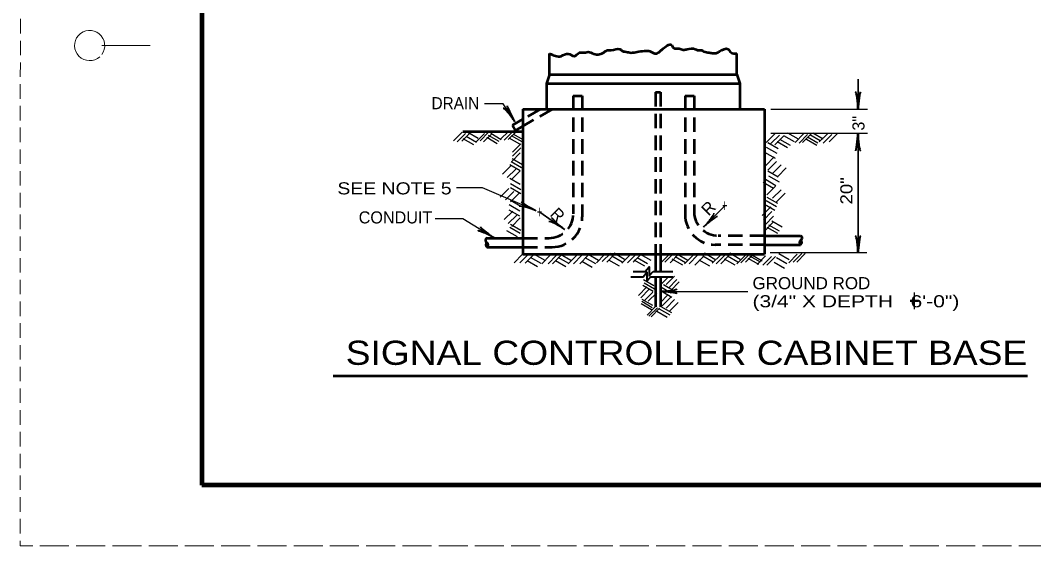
# Model space of a CAD drawing. Extents: x -560 to 120, y 26 to 466.
# Drawn here: x -559.8 to -392.1, y 25.8 to 112.8 of the extents above; entities that cross this region are included whole.
import ezdxf
from ezdxf.enums import TextEntityAlignment as Align

# ---------------------------------------------------------------- set-up
doc = ezdxf.new("R2010")
doc.units = 0
doc.header["$LTSCALE"] = 0.8
doc.linetypes.add('LONG_DASHED', pattern=[7.5, 6, -1.5])
doc.linetypes.add('MEDIUM_DASHED', pattern=[4.5, 3, -1.5])
doc.layers.add('1', color=7, linetype='Continuous', lineweight=53)
doc.layers.add('61', color=7, linetype='Continuous', lineweight=35)

msp = doc.modelspace()

# ---------------------------------------------------------------- linework, layer by layer
at = {"layer": '1', "linetype": 'MEDIUM_DASHED', "lineweight": 13}
msp.add_line((-559.7809, 465.8427), (-559.8409, 25.8027), dxfattribs=at)
at = {"layer": '1'}
for p, q in [((-472.2157, 103.8309), (-472.2157, 107.3309)), ((-441.2157, 103.8309), (-441.2157, 107.3309)), ((-472.2157, 103.8309), (-472.7398, 102.3537)), ((-472.7398, 102.3537), (-440.7398, 102.3537)), ((-472.7398, 102.3537), (-472.7398, 98.1129)), ((-472.2157, 103.8309), (-441.2157, 103.8309)), ((-441.2157, 103.8309), (-440.7398, 102.3537)), ((-440.7398, 102.3537), (-440.7398, 98.1129)), ((-476.6468, 98.1129), (-436.6468, 98.1129)), ((-476.6468, 98.1129), (-476.6468, 74.1129)), ((-436.6468, 98.1129), (-436.6468, 74.1129)), ((-476.6468, 96.4435), (-478.3853, 95.4398)), ((-486.6117, 94.4281), (-476.6117, 94.4281)), ((-478.3853, 95.4398), (-477.8853, 94.5738)), ((-476.6468, 95.2888), (-477.8853, 94.5738)), ((-482.6027, 76.7666), (-476.6027, 76.7666)), ((-436.6707, 77.1478), (-430.6707, 77.1478)), ((-436.6707, 75.6478), (-430.6707, 75.6478)), ((-482.6027, 75.2666), (-476.6027, 75.2666)), ((-476.6468, 74.1129), (-436.6468, 74.1129)), ((-454.6867, 74.117), (-454.6867, 71.2104)), ((-453.8767, 74.1885), (-453.8767, 71.1885)), ((-454.6867, 70.3289), (-454.6867, 65.3528)), ((-453.8868, 70.3528), (-453.8868, 65.3528)), ((-508.0665, 53.9485), (-393.1339, 53.9485))]:
    msp.add_line(p, q, dxfattribs=at)
at = {"layer": '1', "lineweight": 35}
for p, q in [((-421.1766, 98.0819), (-421.1766, 103.0819)), ((-421.1766, 94.0793), (-421.1766, 74.256)), ((-469.7319, 78.1861), (-473.8277, 81.054)), ((-446.7648, 78.5674), (-443.2293, 82.1029))]:
    msp.add_line(p, q, dxfattribs=at)
at = {"layer": '1', "linetype": 'MEDIUM_DASHED'}
for p, q in [((-454.6767, 100.9313), (-453.8767, 100.9313)), ((-454.6767, 100.9313), (-454.6767, 74.1129)), ((-453.8767, 100.9313), (-453.8767, 74.1129)), ((-468.3086, 100.329), (-468.3086, 80.7666)), ((-468.3086, 100.329), (-466.8086, 100.329)), ((-466.8086, 100.329), (-466.8086, 80.2666)), ((-449.8086, 100.329), (-449.8086, 80.6478)), ((-449.8086, 100.329), (-448.3086, 100.329)), ((-448.3086, 100.329), (-448.3086, 81.1478)), ((-473.7553, 98.1129), (-476.6468, 96.4436)), ((-471.7551, 98.1129), (-476.6468, 95.2888)), ((-476.6027, 76.7666), (-472.3086, 76.7666)), ((-436.6707, 75.6478), (-444.8086, 75.6478)), ((-436.6707, 77.1478), (-444.3086, 77.1478)), ((-476.6027, 75.2666), (-471.8086, 75.2666))]:
    msp.add_line(p, q, dxfattribs=at)
at = {"layer": '1', "lineweight": 25}
for p, q in [((-435.6148, 98.1037), (-419.6148, 98.1037)), ((-486.6952, 94.2917), (-488.1094, 92.8774)), ((-486.1233, 94.1011), (-487.5376, 92.6868)), ((-485.361, 94.1963), (-486.7752, 92.7821)), ((-484.0268, 93.2434), (-485.7589, 94.2434)), ((-482.9785, 94.1011), (-484.3927, 92.6868)), ((-482.3113, 94.2917), (-483.7256, 92.8774)), ((-481.7396, 94.1011), (-483.1538, 92.6868)), ((-480.2149, 93.0528), (-481.947, 94.0528)), ((-478.9759, 94.4823), (-480.3902, 93.0681)), ((-478.3088, 94.387), (-479.7231, 92.9727)), ((-477.6418, 94.4823), (-479.056, 93.0681)), ((-476.4982, 92.9575), (-478.2303, 93.9575)), ((-434.9477, 94.0057), (-436.362, 92.5915)), ((-435.6148, 94.1037), (-419.6148, 94.1037)), ((-431.0405, 93.1481), (-432.7726, 94.1481)), ((-430.1827, 94.0058), (-431.597, 92.5916)), ((-428.9439, 94.0058), (-430.3582, 92.5916)), ((-426.9426, 93.1482), (-428.6747, 94.1482)), ((-426.1802, 94.1011), (-427.5944, 92.6868)), ((-424.5601, 94.1011), (-425.9743, 92.6868)), ((-484.7892, 92.1952), (-486.5213, 93.1952)), ((-484.3127, 92.5763), (-486.0447, 93.5763)), ((-480.882, 92.3858), (-482.6141, 93.3858)), ((-480.5961, 92.7669), (-482.3282, 93.7669)), ((-477.1652, 92.2904), (-478.8973, 93.2904)), ((-476.7841, 92.6716), (-478.5162, 93.6716)), ((-476.9747, 92.3858), (-478.3889, 90.9715)), ((-434.376, 91.528), (-436.1081, 92.528)), ((-434.1853, 93.8152), (-435.5996, 92.4009)), ((-433.5182, 93.6246), (-434.9325, 92.2103)), ((-432.8512, 91.7186), (-434.5832, 92.7186)), ((-432.3747, 92.0998), (-434.1067, 93.0998)), ((-431.7076, 92.6716), (-433.4397, 93.6716)), ((-429.5157, 93.9105), (-430.9299, 92.4963)), ((-427.9909, 92.0998), (-429.723, 93.0998)), ((-427.8003, 92.4811), (-429.5323, 93.4811)), ((-427.4191, 92.8623), (-429.1512, 93.8623)), ((-425.5131, 93.9105), (-426.9273, 92.4963)), ((-477.0699, 90.8609), (-478.4842, 89.4467)), ((-476.9747, 91.7187), (-478.3889, 90.3044)), ((-434.8525, 89.9079), (-436.5846, 90.9079)), ((-434.5666, 90.7656), (-436.2987, 91.7656)), ((-476.8793, 88.3832), (-478.6114, 89.3832)), ((-476.6887, 88.8597), (-478.4208, 89.8597)), ((-435.043, 90.1938), (-436.4572, 88.7796)), ((-434.6618, 89.4314), (-436.0761, 88.0172)), ((-478.5947, 88.7643), (-480.009, 87.3501)), ((-477.8323, 88.1925), (-479.2466, 86.7782)), ((-477.0699, 87.9067), (-478.802, 88.9067)), ((-477.07, 87.9067), (-478.4842, 86.4924)), ((-434.3759, 86.8584), (-436.108, 87.8584)), ((-433.8994, 88.8596), (-435.3137, 87.4453)), ((-433.0417, 88.3831), (-434.456, 86.9688)), ((-477.07, 85.6195), (-478.8021, 86.6195)), ((-476.9747, 84.7617), (-478.7067, 85.7617)), ((-435.1383, 84.9523), (-436.8704, 85.9523)), ((-434.7572, 85.4289), (-436.4892, 86.4289)), ((-434.1853, 86.0007), (-435.9174, 87.0007)), ((-483.3361, 85.0857), (-487.6288, 85.0857)), ((-474.4419, 81.2873), (-483.3361, 85.0857)), ((-478.9759, 84.9523), (-480.3902, 83.5381)), ((-478.1182, 84.4758), (-479.5325, 83.0616)), ((-476.9747, 84.0947), (-478.7067, 85.0947)), ((-477.2606, 84.1899), (-478.6748, 82.7757)), ((-434.8524, 85.3336), (-436.2667, 83.9193)), ((-433.8994, 84.7618), (-435.3137, 83.3476)), ((-433.2323, 84.19), (-434.6466, 82.7758)), ((-477.1652, 81.2357), (-478.8973, 82.2357)), ((-476.9747, 81.9982), (-478.7067, 82.9982)), ((-434.9477, 81.331), (-436.6798, 82.331)), ((-434.6619, 81.9028), (-436.394, 82.9028)), ((-434.4712, 82.4746), (-436.2033, 83.4746)), ((-478.3088, 81.2357), (-479.7231, 79.8215)), ((-477.6418, 80.5687), (-479.056, 79.1544)), ((-477.1652, 80.3781), (-478.8973, 81.3781)), ((-435.6148, 81.9028), (-437.0291, 80.4886)), ((-435.4242, 81.1404), (-436.8384, 79.7262)), ((-476.9747, 77.9956), (-478.7067, 78.9956)), ((-477.0699, 80.0922), (-478.4842, 78.6779)), ((-435.1382, 80.378), (-436.5525, 78.9637)), ((-435.1382, 79.425), (-436.5525, 78.0108)), ((-434.1854, 77.9002), (-435.9175, 78.9002)), ((-433.7089, 78.5673), (-435.441, 79.5673)), ((-477.5464, 76.9472), (-479.2785, 77.9472)), ((-477.0699, 77.5191), (-478.802, 78.5191)), ((-434.4712, 77.5191), (-436.2033, 78.5191)), ((-476.6887, 74.0883), (-478.103, 72.674)), ((-475.7357, 74.0883), (-477.15, 72.674)), ((-474.8781, 73.993), (-476.2923, 72.5787)), ((-472.9721, 73.04), (-474.7042, 74.04)), ((-472.1144, 73.8977), (-473.5287, 72.4834)), ((-471.0661, 73.8977), (-472.4803, 72.4834)), ((-470.3037, 73.8977), (-471.7179, 72.4834)), ((-468.6837, 73.04), (-470.4158, 74.04)), ((-467.7306, 73.8977), (-469.1448, 72.4834)), ((-466.8729, 73.8977), (-468.2872, 72.4834)), ((-465.8246, 73.8977), (-467.2388, 72.4834)), ((-464.1092, 73.04), (-465.8413, 74.04)), ((-463.061, 74.0883), (-464.4752, 72.674)), ((-462.108, 74.2788), (-463.5222, 72.8646)), ((-461.3456, 74.1836), (-462.7598, 72.7693)), ((-459.8208, 73.2307), (-461.5529, 74.2307)), ((-458.8678, 73.9929), (-460.2821, 72.5787)), ((-457.9148, 74.0883), (-459.3291, 72.674)), ((-456.9618, 74.1835), (-458.3761, 72.7692)), ((-455.4371, 73.04), (-457.1692, 74.04)), ((-452.3875, 74.0883), (-453.8017, 72.674)), ((-451.7204, 74.1836), (-453.1347, 72.7693)), ((-450.8628, 74.0883), (-452.277, 72.674)), ((-449.3379, 73.04), (-451.07, 74.04)), ((-448.4802, 73.8978), (-449.8944, 72.4835)), ((-447.7177, 73.8978), (-449.132, 72.4835)), ((-444.8588, 73.2307), (-446.5909, 74.2307)), ((-443.9058, 73.993), (-445.3201, 72.5787)), ((-443.2387, 73.8977), (-444.653, 72.4834)), ((-442.4763, 73.8977), (-443.8906, 72.4834)), ((-440.6657, 73.2306), (-442.3977, 74.2306)), ((-439.8079, 73.8977), (-441.2222, 72.4834)), ((-439.1408, 74.0883), (-440.5551, 72.674)), ((-438.3784, 74.1835), (-439.7927, 72.7692)), ((-437.0443, 72.9447), (-438.7764, 73.9447)), ((-435.7101, 74.3767), (-419.7101, 74.3767)), ((-432.5652, 73.1353), (-434.2973, 74.1353)), ((-431.231, 74.0883), (-432.6452, 72.674)), ((-430.4687, 74.1836), (-431.8829, 72.7693)), ((-429.8968, 74.1836), (-431.3111, 72.7693)), ((-474.211, 71.9917), (-475.9431, 72.9917)), ((-473.6393, 72.5635), (-475.3713, 73.5635)), ((-469.5413, 71.9917), (-471.2734, 72.9917)), ((-469.0648, 72.5635), (-470.7969, 73.5635)), ((-465.1576, 71.8964), (-466.8897, 72.8964)), ((-464.5857, 72.4682), (-466.3178, 73.4682)), ((-460.6785, 72.0871), (-462.4106, 73.0871)), ((-460.202, 72.7542), (-461.9341, 73.7542)), ((-456.4853, 72.0871), (-458.2174, 73.0871)), ((-456.0089, 72.4682), (-457.741, 73.4682)), ((-450.1957, 72.2777), (-451.9278, 73.2777)), ((-449.7192, 72.6588), (-451.4512, 73.6588)), ((-446.7647, 73.7071), (-448.179, 72.2928)), ((-445.7165, 72.0871), (-447.4486, 73.0871)), ((-445.1447, 72.7542), (-446.8768, 73.7542)), ((-441.5234, 72.2776), (-443.2555, 73.2776)), ((-441.0469, 72.7541), (-442.779, 73.7541)), ((-437.6161, 72.3729), (-439.3482, 73.3729)), ((-437.3302, 72.7541), (-439.0623, 73.7541)), ((-436.4725, 73.8023), (-437.8868, 72.3881)), ((-435.5195, 73.7071), (-436.9337, 72.2928)), ((-434.8524, 73.7071), (-436.2667, 72.2928)), ((-433.3277, 71.7058), (-435.0598, 72.7058)), ((-432.9464, 72.4682), (-434.6785, 73.4682)), ((-451.5297, 70.4669), (-452.944, 69.0527)), ((-455.0558, 67.8938), (-456.7879, 68.8938)), ((-454.9605, 68.8468), (-456.6926, 69.8468)), ((-454.8653, 68.275), (-456.5973, 69.275)), ((-452.4828, 70.3716), (-453.897, 68.9573)), ((-451.6251, 67.9892), (-453.3572, 68.9892)), ((-451.1485, 69.8951), (-452.5627, 68.4808)), ((-450.7673, 69.5139), (-452.1816, 68.0997)), ((-456.1042, 68.6562), (-457.5184, 67.2419)), ((-455.7229, 68.275), (-457.1372, 66.8607)), ((-455.1512, 67.7985), (-456.5654, 66.3842)), ((-454.484, 67.7032), (-455.8982, 66.289)), ((-452.578, 67.4173), (-453.9923, 66.0031)), ((-453.9837, 67.9317), (-439.4027, 67.9317)), ((-452.1016, 67.6437), (-453.8337, 68.6437)), ((-452.0063, 66.9409), (-453.7384, 67.9409)), ((-455.3417, 64.8443), (-457.0738, 65.8443)), ((-455.2465, 65.2255), (-456.9786, 66.2255)), ((-455.1512, 65.6067), (-456.8832, 66.6067)), ((-452.1969, 66.9408), (-453.6112, 65.5266)), ((-451.5298, 66.5597), (-452.9441, 65.1454)), ((-450.958, 66.0832), (-452.3723, 64.6689)), ((-454.6746, 65.416), (-456.0888, 64.0018)), ((-454.3887, 65.2254), (-455.803, 63.8112)), ((-454.0075, 65.1301), (-455.4217, 63.7158)), ((-452.7687, 63.6053), (-454.5007, 64.6053)), ((-452.2922, 63.9866), (-454.0242, 64.9866)), ((-452.0062, 64.3678), (-453.7383, 65.3678))]:
    msp.add_line(p, q, dxfattribs=at)
at = {"layer": '1', "lineweight": 40}
for p, q in [((-455.094, 71.2426), (-454.7106, 71.2426)), ((-454.6867, 71.2426), (-451.8277, 71.2426))]:
    msp.add_line(p, q, dxfattribs=at)
at = {"layer": '1', "lineweight": 25}
for points in [[(-477.9992, 96.0452), (-479.9052, 98.9995), (-482.9786, 98.9995)], [(-481.4301, 76.7946), (-486.5762, 79.9395), (-491.1517, 79.9395)]]:
    msp.add_lwpolyline(points, dxfattribs=at)
at = {"layer": '1', "lineweight": 40}
for points in [[(-458.7607, 70.3289), (-456.7607, 70.3289), (-456.118, 71.095), (-456.118, 69.595), (-455.4752, 70.3611), (-451.8277, 70.3611)], [(-458.3795, 71.2104), (-456.3795, 71.2104), (-455.7367, 71.9765), (-455.7367, 70.4765), (-455.094, 71.2426)]]:
    msp.add_lwpolyline(points, dxfattribs=at)
at = {"layer": '1', "linetype": 'MEDIUM_DASHED'}
for centre, radius, start, end in [((-472.3086, 80.7666), 4, 270, 0), ((-444.8086, 80.6478), 5, 180, 270), ((-444.3086, 81.1478), 4, 180, 270), ((-471.8086, 80.2666), 5, 270, 0)]:
    msp.add_arc(centre, radius, start, end, dxfattribs=at)
at = {"layer": '1'}
for centre, start, end in [((-482.345, 75.6244), 121.91368, 234.28887), ((-482.825, 75.6244), 305.71113, 58.08632), ((-430.4435, 76.0294), 121.91368, 234.28887), ((-430.9235, 76.0294), 305.71113, 58.08632)]:
    msp.add_arc(centre, 0.4314, start, end, dxfattribs=at)
at = {"layer": '1', "lineweight": 40}
for centre, major_axis, ratio, start_param, end_param in [((-421.4529, 99.1731), (0.1562, -1.7857), 0.122415, 0.89635335, 3.14159265), ((-420.965, 99.2024), (0.1757, 1.7565), 0.07063, 6.28230741, 8.55970261), ((-478.823, 96.8123), (1.0993, -1.4159), 0.122415, 0.89635335, 3.14159265), ((-478.4289, 97.1014), (0.8046, -1.5712), 0.07063, 3.14071475, 5.41810995), ((-421.3882, 92.9588), (-0.1757, -1.7565), 0.07063, 6.28230741, 8.55970261), ((-420.9003, 92.9881), (-0.1562, 1.7857), 0.122415, 0.89635335, 3.14159265), ((-482.5053, 77.1278), (1.6051, -0.7979), 0.122415, 0.89635335, 3.14159265), ((-482.2758, 77.5594), (-1.4071, 1.0658), 0.07063, 6.28230741, 8.55970261), ((-421.4529, 75.3472), (0.1562, -1.7857), 0.122415, 0.89635335, 3.14159265), ((-420.965, 75.3765), (0.1757, 1.7565), 0.07063, 6.28230741, 8.55970261), ((-452.8632, 67.7201), (1.7565, -0.1757), 0.07063, 6.28230741, 8.55970261), ((-452.8925, 68.208), (-1.7857, -0.1562), 0.122415, 0.89635335, 3.14159265)]:
    msp.add_ellipse(centre, major_axis=major_axis, ratio=ratio, start_param=start_param, end_param=end_param, dxfattribs=at)
at = {"layer": '1', "lineweight": 35}
for centre, major_axis, ratio, start_param, end_param in [((-475.3893, 81.9219), (-1.5463, 0.8514), 0.07063, 6.28230741, 8.55970261), ((-475.554, 81.4617), (1.7035, -0.5577), 0.122415, 0.89635335, 3.14159265), ((-446.1886, 79.5344), (-1.1523, -1.3731), 0.122415, 0.89635335, 3.14159265), ((-470.7843, 78.5856), (1.5523, -0.8963), 0.122415, 0.89635335, 3.14159265), ((-470.5284, 79.0021), (1.338, -1.1514), 0.07063, 3.14071475, 5.41810995), ((-445.8229, 79.2101), (1.3662, 1.1178), 0.07063, 6.28230741, 8.55970261)]:
    msp.add_ellipse(centre, major_axis=major_axis, ratio=ratio, start_param=start_param, end_param=end_param, dxfattribs=at)
at = {"layer": '1'}
for centre, major_axis, start_param, end_param in [((-430.9175, 76.8213), (-0.4135, 0.2973), 2.61207212, 4.71238898), ((-482.351, 76.4163), (0.4135, 0.2973), 1.57079633, 3.67111319)]:
    msp.add_ellipse(centre, major_axis=major_axis, ratio=0.847055, start_param=start_param, end_param=end_param, dxfattribs=at)
msp.add_spline([(-472.2157, 107.3309), (-470.3098, 106.9043), (-469.1662, 107.2855), (-468.118, 106.9043), (-467.2604, 107.4761), (-466.498, 107.4761), (-465.6403, 107.5714), (-464.6874, 107.1902), (-463.7345, 107.2855), (-463.4486, 107.3808), (-462.6862, 107.8572), (-462.0192, 107.8572), (-460.5897, 108.0479), (-460.2086, 107.762), (-459.3509, 107.5714), (-458.9697, 107.4761), (-458.4932, 107.4761), (-457.445, 107.6667), (-456.2062, 107.762), (-455.825, 107.762), (-454.9674, 107.3808), (-454.3956, 107.3808), (-454.1097, 107.5714), (-453.6332, 107.9526), (-452.0132, 108.7149), (-451.7273, 108.2385), (-450.7744, 108.1432), (-450.1073, 107.9526), (-449.4402, 108.0479), (-448.1062, 108.0479), (-447.6297, 107.8572), (-447.0579, 107.8572), (-446.6767, 107.6667), (-445.8191, 107.4761), (-445.152, 107.3808), (-444.6756, 107.3808), (-444.1038, 107.6667), (-442.6744, 108.0479), (-442.1979, 107.4761), (-441.2157, 107.3309)], degree=3, dxfattribs=at)
at = {"layer": '61', "lineweight": 13}
msp.add_line((-546.3409, 108.6427), (-538.3609, 108.6427), dxfattribs=at)
at = {"layer": '61', "lineweight": 158}
msp.add_line((109.2791, 35.8027), (-529.7809, 35.8227), dxfattribs=at)
at = {"layer": '61', "linetype": 'LONG_DASHED', "lineweight": 13}
msp.add_line((120.2191, 25.8227), (-559.8409, 25.8027), dxfattribs=at)
at = {"layer": '61', "lineweight": 158}
msp.add_lwpolyline([(109.2591, 455.8427), (-529.7809, 455.8427), (-529.7809, 35.8227)], dxfattribs=at)
at = {"layer": '61', "lineweight": 13}
msp.add_arc((-548.3632, 108.644), 2.5, 323.13009, 312.31439, dxfattribs=at)

# ---------------------------------------------------------------- texts
at = {"layer": '1'}
for s, width, p in [('DRAIN', 0.95, (-487.8152, 98.0948)), ('+', 0.55, (-443.2265, 81.1657)), ('+', 0.55, (-473.8893, 80.0935))]:
    msp.add_text(s, height=2, dxfattribs=dict(at, width=width)).set_placement(p, align=Align.CENTER)
msp.add_text('3"', height=2, rotation=90, dxfattribs=at).set_placement((-420.1052, 94.5507))
for s, height, width, p in [('SEE NOTE 5', 2, 1.2, (-507.3517, 83.9903)), ('GROUND ROD', 2, 1.05, (-438.6404, 68.2889)), ('(3/4" X DEPTH   6\'-0")', 2, 1.3, (-438.6404, 65.2889)), ('+', 4, 0.55, (-412.7287, 64.4357)), ('SIGNAL CONTROLLER CABINET BASE', 4, 1.15, (-505.9698, 55.7605))]:
    msp.add_text(s, height=height, dxfattribs=dict(at, width=width)).set_placement(p)
at = {"layer": '1', "width": 1.15}
msp.add_text('20"', height=2, rotation=90, dxfattribs=at).set_placement((-422.1065, 82.3224))
at = {"layer": '1'}
for rotation, p in [(45, (-445.221, 81.0096)), (315, (-471.6039, 79.9084))]:
    msp.add_text('R', height=2, rotation=rotation, dxfattribs=at).set_placement(p, align=Align.CENTER)
msp.add_text('CONDUIT', height=2, dxfattribs=at).set_placement((-503.8257, 79.1779))

doc.saveas('drawing.dxf')
